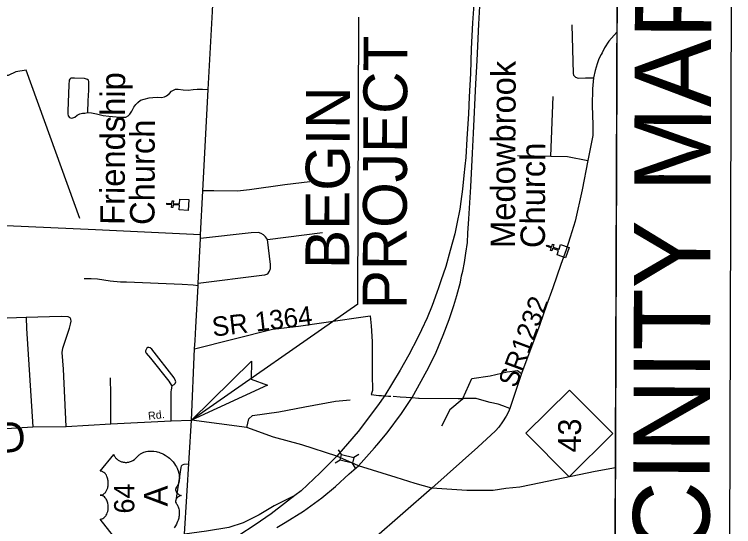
# Model space of a CAD drawing. Extents: x 2364794 to 2387902, y 795230 to 810426.
# Drawn here: x 2366377 to 2367318, y 801114 to 801786 of the extents above; entities that cross this region are included whole.
import ezdxf

# ---------------------------------------------------------------- set-up
doc = ezdxf.new("R2010")
doc.units = 0
for name, color, linetype in [('Default', 7, 'Continuous'), ('Old_Level_10', 7, 'Continuous'), ('Plot Label CELL', 7, 'Continuous'), ('Plot Shape CELL', 7, 'Continuous'), ('User Information Notes CELL', 7, 'Continuous')]:
    doc.layers.add(name, color=color, linetype=linetype)

msp = doc.modelspace()

# ---------------------------------------------------------------- linework, layer by layer
at = {"layer": 'Default'}
for p, q in [((2367310.68, 800398.89), (2367318.28, 802550.69)), ((2366826.27, 801406.05), (2366827.6, 801781.94)), ((2366826.27, 801406.05), (2366608.57, 801253.98)), ((2367046.3, 801236.64), (2367103.4, 801293.34)), ((2367103.4, 801293.34), (2367160.09, 801236.24)), ((2366843.94, 801287.32), (2366853.87, 801286.37)), ((2366897.38, 801283.49), (2366905.75, 801282.89)), ((2367103, 801179.55), (2367046.3, 801236.64)), ((2367160.09, 801236.24), (2367103, 801179.55)), ((2366489.2, 801187.02), (2366506.78, 801208.93)), ((2366506.78, 801208.93), (2366506.98, 801208.41)), ((2366506.98, 801208.41), (2366507.56, 801207.21)), ((2366538.58, 801207.19), (2366540.18, 801208.56)), ((2366540.18, 801208.56), (2366540.93, 801209.11)), ((2366540.93, 801209.11), (2366541.78, 801209.67)), ((2366541.78, 801209.67), (2366542.65, 801210.19)), ((2366542.65, 801210.19), (2366543.59, 801210.71)), ((2366543.59, 801210.71), (2366544.41, 801211.12)), ((2366544.41, 801211.12), (2366546.29, 801211.88)), ((2366546.29, 801211.88), (2366548.12, 801212.44)), ((2366548.12, 801212.44), (2366549.09, 801212.7)), ((2366549.09, 801212.7), (2366551.24, 801213.1)), ((2366551.24, 801213.1), (2366552.31, 801213.25)), ((2366552.31, 801213.25), (2366554.41, 801213.41)), ((2366554.41, 801213.41), (2366556.96, 801213.41)), ((2366556.96, 801213.41), (2366559.37, 801213.21)), ((2366559.37, 801213.21), (2366562.19, 801212.74)), ((2366562.19, 801212.74), (2366563.87, 801212.36)), ((2366563.87, 801212.36), (2366565.83, 801211.78)), ((2366565.83, 801211.78), (2366567.53, 801211.21)), ((2366567.53, 801211.21), (2366570.03, 801210.2)), ((2366570.03, 801210.2), (2366571.85, 801209.3)), ((2366571.85, 801209.3), (2366573.97, 801208.14)), ((2366573.97, 801208.14), (2366575.25, 801207.34)), ((2366804.94, 801208.71), (2366800.96, 801215.12)), ((2366827.47, 801209.04), (2366821.05, 801205.06)), ((2366507.56, 801207.21), (2366508.11, 801206.26)), ((2366508.11, 801206.26), (2366509.17, 801204.75)), ((2366509.17, 801204.75), (2366509.76, 801204.1)), ((2366509.76, 801204.1), (2366510.36, 801203.45)), ((2366510.36, 801203.45), (2366511.01, 801202.85)), ((2366511.01, 801202.85), (2366511.62, 801202.32)), ((2366511.62, 801202.32), (2366512.5, 801201.68)), ((2366512.5, 801201.68), (2366513.38, 801201.11)), ((2366513.38, 801201.11), (2366514.35, 801200.55)), ((2366514.35, 801200.55), (2366515.19, 801200.13)), ((2366515.19, 801200.13), (2366516.96, 801199.45)), ((2366516.96, 801199.45), (2366518.07, 801199.12)), ((2366518.07, 801199.12), (2366519.02, 801198.91)), ((2366519.02, 801198.91), (2366520.98, 801198.65)), ((2366520.98, 801198.65), (2366521.91, 801198.58)), ((2366522.84, 801198.58), (2366523.81, 801198.62)), ((2366523.81, 801198.62), (2366524.75, 801198.71)), ((2366524.75, 801198.71), (2366525.72, 801198.88)), ((2366525.72, 801198.88), (2366526.58, 801199.03)), ((2366526.58, 801199.03), (2366527.63, 801199.3)), ((2366527.63, 801199.3), (2366528.85, 801199.68)), ((2366528.85, 801199.68), (2366530.03, 801200.16)), ((2366530.03, 801200.16), (2366531.95, 801201.16)), ((2366531.95, 801201.16), (2366533.9, 801202.44)), ((2366533.9, 801202.44), (2366534.99, 801203.36)), ((2366534.99, 801203.36), (2366535.93, 801204.26)), ((2366535.93, 801204.26), (2366537.08, 801205.62)), ((2366537.08, 801205.62), (2366537.73, 801206.35)), ((2366537.73, 801206.35), (2366538.58, 801207.19)), ((2366575.25, 801207.34), (2366576.63, 801206.42)), ((2366576.63, 801206.42), (2366578.21, 801205.26)), ((2366578.21, 801205.26), (2366579.89, 801203.9)), ((2366579.89, 801203.9), (2366581.66, 801202.27)), ((2366581.66, 801202.27), (2366582.97, 801200.96)), ((2366582.97, 801200.96), (2366584.5, 801199.24)), ((2366584.5, 801199.24), (2366585.35, 801198.2)), ((2366803.21, 801201.36), (2366796.8, 801197.39)), ((2366521.91, 801198.58), (2366522.84, 801198.58)), ((2366585.35, 801198.2), (2366586.46, 801196.72)), ((2366586.46, 801196.72), (2366587.8, 801194.69)), ((2366587.8, 801194.69), (2366588.95, 801192.68)), ((2366588.95, 801192.68), (2366589.82, 801190.98)), ((2366589.82, 801190.98), (2366590.46, 801189.47)), ((2366590.46, 801189.47), (2366591.19, 801187.52)), ((2366823.26, 801191.14), (2366819.29, 801197.55)), ((2366489.86, 801186.99), (2366489.2, 801187.02)), ((2366490.62, 801186.89), (2366489.86, 801186.99)), ((2366491.5, 801186.67), (2366490.62, 801186.89)), ((2366492.33, 801186.32), (2366491.5, 801186.67)), ((2366493.12, 801185.94), (2366492.33, 801186.32)), ((2366493.89, 801185.4), (2366493.12, 801185.94)), ((2366494.94, 801184.49), (2366493.89, 801185.4)), ((2366495.82, 801183.53), (2366494.94, 801184.49)), ((2366496.46, 801182.72), (2366495.82, 801183.53)), ((2366497.15, 801181.62), (2366496.46, 801182.72)), ((2366497.86, 801180.25), (2366497.15, 801181.62)), ((2366498.31, 801179.2), (2366497.86, 801180.25)), ((2366591.19, 801187.52), (2366592.08, 801184.28)), ((2366592.08, 801184.28), (2366592.32, 801183.1)), ((2366592.32, 801183.1), (2366592.52, 801181.69)), ((2366592.52, 801181.69), (2366592.65, 801180.38)), ((2366592.65, 801180.38), (2366592.72, 801179.11)), ((2366498.73, 801178), (2366498.31, 801179.2)), ((2366499.08, 801176.68), (2366498.73, 801178)), ((2366499.29, 801175.68), (2366499.08, 801176.68)), ((2366499.5, 801174.43), (2366499.29, 801175.68)), ((2366499.62, 801173.3), (2366499.5, 801174.43)), ((2366499.68, 801172.2), (2366499.62, 801173.3)), ((2366499.66, 801170.03), (2366499.69, 801171)), ((2366499.69, 801171), (2366499.68, 801172.2)), ((2366591.46, 801170.67), (2366590.83, 801169.08)), ((2366591.98, 801172.42), (2366591.46, 801170.67)), ((2366592.34, 801174.09), (2366591.98, 801172.42)), ((2366592.58, 801175.7), (2366592.34, 801174.09)), ((2366592.71, 801177.4), (2366592.58, 801175.7)), ((2366592.72, 801179.11), (2366592.71, 801177.4)), ((2366497, 801160.78), (2366497.88, 801162.52)), ((2366497.88, 801162.52), (2366498.26, 801163.38)), ((2366498.26, 801163.38), (2366498.58, 801164.26)), ((2366498.58, 801164.26), (2366498.92, 801165.38)), ((2366498.92, 801165.38), (2366499.2, 801166.53)), ((2366499.2, 801166.53), (2366499.4, 801167.67)), ((2366499.4, 801167.67), (2366499.57, 801168.84)), ((2366499.57, 801168.84), (2366499.66, 801170.03)), ((2366587.77, 801163.54), (2366587.72, 801162.49)), ((2366587.72, 801162.49), (2366587.92, 801161.5)), ((2366587.89, 801163.98), (2366587.77, 801163.54)), ((2366588.31, 801164.76), (2366587.89, 801163.98)), ((2366587.92, 801161.5), (2366588.32, 801160.49)), ((2366590.03, 801167.47), (2366588.31, 801164.76)), ((2366590.83, 801169.08), (2366590.03, 801167.47)), ((2366489.11, 801155.58), (2366490.14, 801155.65)), ((2366490.33, 801155.48), (2366489.11, 801155.58)), ((2366490.14, 801155.65), (2366490.77, 801155.75)), ((2366490.91, 801155.35), (2366490.33, 801155.48)), ((2366490.77, 801155.75), (2366491.4, 801155.92)), ((2366492.24, 801154.88), (2366490.91, 801155.35)), ((2366491.4, 801155.92), (2366492.06, 801156.17)), ((2366492.06, 801156.17), (2366492.99, 801156.64)), ((2366492.86, 801154.54), (2366492.24, 801154.88)), ((2366493.51, 801154.15), (2366492.86, 801154.54)), ((2366492.99, 801156.64), (2366493.78, 801157.15)), ((2366494.66, 801153.22), (2366493.51, 801154.15)), ((2366493.78, 801157.15), (2366494.93, 801158.13)), ((2366495.77, 801152.05), (2366494.66, 801153.22)), ((2366494.93, 801158.13), (2366495.51, 801158.74)), ((2366495.51, 801158.74), (2366495.96, 801159.29)), ((2366496.36, 801151.22), (2366495.77, 801152.05)), ((2366495.96, 801159.29), (2366497, 801160.78)), ((2366588.32, 801160.49), (2366588.64, 801159.87)), ((2366588.64, 801159.87), (2366589.17, 801159.06)), ((2366589.73, 801152.04), (2366589.05, 801151.21)), ((2366589.17, 801159.06), (2366589.66, 801158.44)), ((2366589.66, 801158.44), (2366590.37, 801157.68)), ((2366590.39, 801152.72), (2366589.73, 801152.04)), ((2366590.37, 801157.68), (2366590.97, 801157.16)), ((2366591.28, 801153.49), (2366590.39, 801152.72)), ((2366590.97, 801157.16), (2366591.43, 801156.76)), ((2366591.97, 801153.97), (2366591.28, 801153.49)), ((2366591.43, 801156.76), (2366592.64, 801155.99)), ((2366592.75, 801154.44), (2366591.97, 801153.97)), ((2366592.64, 801155.99), (2366593.21, 801155.72)), ((2366593.66, 801154.83), (2366592.75, 801154.44)), ((2366593.21, 801155.72), (2366593.95, 801155.43)), ((2366595.04, 801155.18), (2366593.66, 801154.83)), ((2366593.95, 801155.43), (2366595.04, 801155.18)), ((2366497.04, 801150.17), (2366496.36, 801151.22)), ((2366497.73, 801148.85), (2366497.04, 801150.17)), ((2366498.22, 801147.66), (2366497.73, 801148.85)), ((2366498.66, 801146.37), (2366498.22, 801147.66)), ((2366498.95, 801145.22), (2366498.66, 801146.37)), ((2366499.42, 801142.72), (2366498.95, 801145.22)), ((2366499.59, 801140.46), (2366499.42, 801142.72)), ((2366587.7, 801148.19), (2366587.65, 801147.54)), ((2366587.65, 801147.54), (2366587.66, 801147.01)), ((2366587.66, 801147.01), (2366587.82, 801146.27)), ((2366587.9, 801148.98), (2366587.7, 801148.19)), ((2366587.82, 801146.27), (2366588.54, 801145.28)), ((2366588.15, 801149.62), (2366587.9, 801148.98)), ((2366588.52, 801150.33), (2366588.15, 801149.62)), ((2366589.05, 801151.21), (2366588.52, 801150.33)), ((2366588.54, 801145.28), (2366589.18, 801144.33)), ((2366589.18, 801144.33), (2366589.82, 801143.31)), ((2366589.82, 801143.31), (2366590.46, 801142.08)), ((2366498.35, 801132.44), (2366498.9, 801134.33)), ((2366498.9, 801134.33), (2366499.3, 801136.26)), ((2366499.3, 801136.26), (2366499.54, 801138.38)), ((2366499.54, 801138.38), (2366499.59, 801140.46)), ((2366590.46, 801142.08), (2366590.87, 801141.19)), ((2366590.87, 801141.19), (2366591.28, 801140.12)), ((2366591.28, 801140.12), (2366591.7, 801138.87)), ((2366591.7, 801138.87), (2366592.04, 801137.52)), ((2366592.04, 801137.52), (2366592.31, 801136.13)), ((2366592.31, 801136.13), (2366592.5, 801134.91)), ((2366592.5, 801134.91), (2366592.61, 801133.6)), ((2366592.61, 801133.6), (2366592.65, 801132.42)), ((2366489.05, 801124.13), (2366489.96, 801124.19)), ((2366506.47, 801102.1), (2366489.05, 801124.13)), ((2366489.96, 801124.19), (2366491.04, 801124.4)), ((2366491.04, 801124.4), (2366491.6, 801124.57)), ((2366491.6, 801124.57), (2366492.66, 801125.07)), ((2366492.66, 801125.07), (2366493.93, 801125.9)), ((2366493.93, 801125.9), (2366495.16, 801127.06)), ((2366495.16, 801127.06), (2366496.24, 801128.36)), ((2366496.24, 801128.36), (2366496.82, 801129.24)), ((2366496.82, 801129.24), (2366497.63, 801130.74)), ((2366497.63, 801130.74), (2366498.35, 801132.44)), ((2366591.45, 801124.21), (2366590.98, 801122.72)), ((2366591.84, 801125.66), (2366591.45, 801124.21)), ((2366592.16, 801127.04), (2366591.84, 801125.66)), ((2366592.41, 801128.7), (2366592.16, 801127.04)), ((2366592.53, 801130.03), (2366592.41, 801128.7)), ((2366592.63, 801131.19), (2366592.53, 801130.03)), ((2366592.65, 801132.42), (2366592.63, 801131.19)), ((2366587.5, 801115.56), (2366585.71, 801112.99)), ((2366588.76, 801117.75), (2366587.5, 801115.56)), ((2366589.48, 801119.13), (2366588.76, 801117.75)), ((2366590.36, 801121.13), (2366589.48, 801119.13)), ((2366590.98, 801122.72), (2366590.36, 801121.13))]:
    msp.add_line(p, q, dxfattribs=at)
for points in [[(2365221.07, 800406.27), (2365228.68, 802558.07), (2367168.28, 802551.22), (2367160.68, 800399.42)], [(2365221.07, 800406.27), (2365228.68, 802558.07), (2367168.28, 802551.22), (2367160.68, 800399.42)], [(2366592.52, 801529.31), (2366592.91, 801535.52), (2366584.6, 801536.06), (2366584.37, 801532.57), (2366582.63, 801532.69), (2366582.86, 801536.18), (2366576.3, 801536.61), (2366576.41, 801538.36), (2366582.98, 801537.93), (2366583.21, 801541.42), (2366584.95, 801541.3), (2366584.72, 801537.81), (2366593.03, 801537.27), (2366593.45, 801543.56), (2366605.07, 801542.79), (2366604.13, 801528.54)], [(2367087.16, 801470.35), (2367089.17, 801476.24), (2367081.3, 801478.95), (2367080.16, 801475.64), (2367078.51, 801476.21), (2367079.65, 801479.52), (2367073.43, 801481.66), (2367074, 801483.32), (2367080.22, 801481.17), (2367081.36, 801484.48), (2367083.01, 801483.91), (2367081.87, 801480.61), (2367089.74, 801477.9), (2367091.81, 801483.85), (2367102.82, 801480.06), (2367098.17, 801466.56)], [(2366819.29, 801197.55), (2366803.2, 801201.33), (2366804.97, 801208.84), (2366821.05, 801205.06)]]:
    msp.add_lwpolyline(points, close=True, dxfattribs=at)
for points in [[(2366853.87, 801286.37), (2366857.53, 801286.02), (2366862.3, 801285.75)], [(2366862.3, 801285.75), (2366866.69, 801285.49), (2366869.76, 801285.33)], [(2366605.33, 801196.12), (2366598.71, 801195.84), (2366596.27, 801195.03), (2366595.25, 801193.82), (2366594.63, 801191.79), (2366587.98, 801148.76)]]:
    msp.add_lwpolyline(points, dxfattribs=at)
at = {"layer": 'Old_Level_10'}
msp.add_line((2367160.68, 800399.42), (2367168.28, 802551.22), dxfattribs=at)
msp.add_lwpolyline([(2366708.16, 801299.72), (2366608.57, 801253.98), (2366687.27, 801331.23), (2366686.75, 801307.59)], close=True, dxfattribs=at)
at = {"layer": 'Plot Label CELL'}
for p, q in [((2367124.55, 801702.37), (2367134.81, 801702.62)), ((2367078.96, 801599.7), (2367082.19, 801678.01)), ((2367035.35, 801600.59), (2367078.96, 801599.7)), ((2366708.19, 801490.49), (2366779.91, 801499.63)), ((2366392.08, 801388.36), (2366349.47, 801386.86)), ((2366502.95, 801287.64), (2366502.71, 801309.18)), ((2366582.34, 801293.23), (2366583.3, 801299.15))]:
    msp.add_line(p, q, dxfattribs=at)
for points in [[(2367106.5, 801771.81), (2367108.36, 801708.21), (2367108.81, 801706.02), (2367109.87, 801704.74), (2367111.34, 801703.26), (2367114.85, 801702.14), (2367124.55, 801702.37)], [(2367165.49, 801762.42), (2367155.03, 801750.39), (2367149.05, 801741.82), (2367146.01, 801735.28), (2367144.71, 801733.07), (2367141.92, 801727.16), (2367140.34, 801723.59), (2367139.49, 801720.89), (2367137.06, 801712.03), (2367134.81, 801702.62), (2367133.56, 801688.22), (2367133.29, 801666.24), (2367134.18, 801640.87), (2367133.89, 801626.7)], [(2366472.83, 801656.82), (2366473.41, 801672.08), (2366474.33, 801686.1), (2366474.37, 801697.16), (2366473.85, 801699.26), (2366472.63, 801700.32), (2366468.6, 801701.56), (2366455.44, 801702.13), (2366450.7, 801701.97), (2366449.29, 801700.58), (2366448.41, 801699.18), (2366448.04, 801693.39), (2366446.68, 801658.84), (2366446.67, 801655.16), (2366447.01, 801652.52), (2366448.76, 801650.24), (2366451.04, 801649.53), (2366453.15, 801649.87), (2366455.96, 801650.91), (2366459.13, 801653.36), (2366462.47, 801655.1), (2366465.8, 801655.97), (2366468.96, 801656.31), (2366472.83, 801656.82)], [(2366472.83, 801656.82), (2366477.74, 801656.63), (2366484.4, 801655.37), (2366493.17, 801652.89), (2366500.54, 801652.16), (2366510.19, 801651.42), (2366518.26, 801650.87), (2366522.65, 801651.03), (2366525.64, 801652.42), (2366527.75, 801654.69), (2366530.4, 801658.72), (2366533.22, 801663.97), (2366535.52, 801667.65), (2366538.33, 801670.27), (2366541.85, 801673.06), (2366546.6, 801674.62), (2366553.1, 801676.18), (2366557.84, 801676.86), (2366563.98, 801677.19), (2366569.24, 801676.82), (2366573.28, 801677.34), (2366575.74, 801678.91), (2366579.62, 801681.87), (2366582.61, 801684.85), (2366584.9, 801686.24), (2366587.53, 801687.63), (2366591.22, 801687.62), (2366597.53, 801686.9), (2366604.2, 801686.35), (2366610.87, 801687.03), (2366616.14, 801687.36), (2366622.98, 801687.51), (2366630.55, 801687.32)], [(2367133.89, 801626.7), (2367127.63, 801594.08), (2367120.2, 801555.77), (2367111, 801514.61), (2367104.36, 801493.85), (2367098.94, 801476.88), (2367092.22, 801457.88), (2367081.58, 801427.34), (2367073.37, 801404.47), (2367064.78, 801379.37), (2367040.76, 801314.82), (2367025.38, 801269.01), (2367023.67, 801264.84), (2367020.67, 801259.33), (2367015.91, 801251.87), (2367010.72, 801244.84), (2367006.38, 801239.75), (2366983.63, 801218.36), (2366923.32, 801164.77)], [(2367078.96, 801599.7), (2367100.95, 801599.43), (2367127.63, 801594.08)], [(2366763.43, 801566.35), (2366730.65, 801562.07), (2366684.47, 801555.56), (2366668.75, 801553.78), (2366637.69, 801554.24), (2366623.48, 801554.46)], [(2366620.55, 801496.5), (2366482.99, 801503.36), (2366336.12, 801509.96), (2366282.43, 801513.49), (2366243.83, 801515.9), (2366150.3, 801521.11), (2366145.19, 801521.38), (2366044.51, 801526.78), (2365939.06, 801532.24), (2365896.96, 801538), (2365863.11, 801543.56), (2365836.88, 801547.42), (2365829.34, 801548.15), (2365823.73, 801548.7), (2365818.81, 801549.06), (2365807.58, 801548.93), (2365800.21, 801548.43)], [(2366617.52, 801433.53), (2366700.67, 801444.04), (2366704.52, 801444.38), (2366708.38, 801445.59), (2366710.68, 801449.27), (2366711.92, 801452.59), (2366711.94, 801458.03), (2366708.19, 801490.49)], [(2366708.19, 801490.49), (2366705.4, 801494.01), (2366702.95, 801496.65), (2366699.8, 801498.59), (2366696.29, 801499.66), (2366686.64, 801499.34), (2366620.36, 801492.12)], [(2366617.3, 801429.91), (2366610.64, 801430.85), (2366596.19, 801431.43), (2366523.73, 801434.67), (2366515.83, 801434.69), (2366502.06, 801435.88), (2366485.6, 801438.46), (2366477.07, 801439.26), (2366468.1, 801439.17)], [(2366444.48, 801245.73), (2366441.01, 801320.88), (2366439.1, 801342.52), (2366440.15, 801348.11), (2366449.06, 801374.27), (2366450.33, 801379.52), (2366450.94, 801383.46), (2366450.7, 801386.07), (2366449.57, 801388.05), (2366447.17, 801389.11), (2366437.77, 801389.66), (2366392.08, 801388.36)], [(2366392.08, 801388.36), (2366392.69, 801373.81), (2366400.79, 801245.11)], [(2366782.03, 801381.92), (2366842.43, 801390.78), (2366843.88, 801377.66), (2366844.94, 801357.09), (2366845.08, 801313.61), (2366845.48, 801292.84), (2366843.94, 801287.32)], [(2366612.63, 801347.25), (2366714.52, 801373.06), (2366748.8, 801377.05), (2366782.03, 801381.92)], [(2366583.3, 801299.15), (2366585.7, 801300.47), (2366587.22, 801301.78), (2366588.08, 801303.98), (2366587.86, 801305.51), (2366586.06, 801309.22), (2366556.66, 801347), (2366554.68, 801348.53), (2366552.94, 801348.95), (2366551.41, 801348.93), (2366550.32, 801348.26), (2366548.38, 801344.53), (2366548.17, 801343.21), (2366549.06, 801341.69), (2366554.81, 801335.19), (2366578.89, 801304.78), (2366582.43, 801299.35), (2366583.3, 801299.15)], [(2366963.59, 801282.09), (2366975.56, 801308.43), (2366999.47, 801312.14), (2367022, 801317.43), (2367035.37, 801318.84), (2367040.76, 801314.82)], [(2366582.15, 801253.06), (2366582.06, 801291.47), (2366582.34, 801293.23)], [(2366502.8, 801248.97), (2366502.8, 801254.52), (2366503.17, 801268.16), (2366502.95, 801287.64)], [(2366872.8, 801285.15), (2366881.93, 801284.59), (2366897.38, 801283.49)], [(2366681.23, 801244.45), (2366683.59, 801255.43), (2366688.26, 801260.06), (2366722.79, 801264.75), (2366757.13, 801271.54), (2366797.02, 801278.79), (2366816.39, 801280.74)], [(2366905.75, 801282.89), (2366906.7, 801282.83), (2366957.49, 801282.3), (2366963.59, 801282.09)], [(2366963.59, 801282.09), (2366962.76, 801281.01), (2366946.95, 801267.51), (2366935.82, 801245.83)], [(2367025.38, 801269.01), (2367015.96, 801272.86), (2367010.03, 801274.78), (2366999.52, 801276.86), (2366988.65, 801280.29), (2366981.11, 801282.11), (2366963.59, 801282.09)], [(2365883.31, 801194.17), (2365923.88, 801198.32), (2366005.19, 801208.19), (2366040.96, 801213.55), (2366060.86, 801216.45), (2366088.81, 801220.19), (2366143.18, 801226.76), (2366187.52, 801232.81), (2366212.86, 801234.35), (2366246.94, 801236.16), (2366291.51, 801239.37), (2366308.13, 801238.86), (2366358.84, 801242.59), (2366400.79, 801245.11), (2366444.48, 801245.73), (2366502.8, 801248.97), (2366582.15, 801253.06), (2366608.57, 801253.98)], [(2366681.23, 801244.45), (2366608.57, 801253.98)], [(2366798.8, 801206.63), (2366752.99, 801221.37), (2366715.84, 801231.64), (2366681.23, 801244.45)], [(2366827.07, 801194.06), (2366798.8, 801206.63)], [(2366923.32, 801164.77), (2366901.37, 801170.77), (2366876.46, 801178.88), (2366827.07, 801194.06)], [(2367163.47, 801191.25), (2367137.03, 801186.42), (2367053.29, 801169.17), (2367038.28, 801166.27), (2367020.1, 801164.22), (2367003.4, 801161.95), (2366968.95, 801161.65), (2366923.32, 801164.77)], [(2366923.32, 801164.77), (2366809.38, 801065.16), (2366769.88, 801030.29), (2366731.88, 800998.7), (2366709.97, 800981.02), (2366639.98, 800922.63), (2366602.18, 800891.19), (2366598.11, 800888.97), (2366593.63, 800886.75), (2366588.34, 800884.74)]]:
    msp.add_lwpolyline(points, dxfattribs=at)
at = {"layer": 'Plot Shape CELL'}
for points in [[(2366620.55, 801496.5), (2366623.48, 801554.46), (2366630.55, 801687.32), (2366635.98, 801789.2), (2366637.22, 801817.52), (2366639.18, 801851.8), (2366640.69, 801880.74), (2366645.59, 801975.26)], [(2366980.2, 801829.83), (2366976.55, 801774.3), (2366974.89, 801740.41), (2366973.64, 801708.18), (2366971.92, 801677.49), (2366971.25, 801655.13), (2366969.15, 801622.66), (2366967.57, 801597.87), (2366966.62, 801586.53), (2366964.99, 801574.5), (2366963.33, 801556.35), (2366961.01, 801540.46), (2366959.84, 801530.48), (2366955.91, 801510.97), (2366953.13, 801498.04), (2366947.38, 801476.27), (2366941.63, 801455.18), (2366935.2, 801436.36), (2366931.76, 801427.29), (2366929.69, 801421.17), (2366923.5, 801403.94), (2366917.31, 801388.07), (2366909.76, 801372.2), (2366904.73, 801362.23), (2366893.29, 801339.57), (2366881.64, 801319.41), (2366861.67, 801286.25), (2366861.53, 801286.11), (2366851.94, 801272.52), (2366826.93, 801238.82), (2366798.8, 801206.63)], [(2366827.07, 801194.06), (2366848.21, 801217.48), (2366851.29, 801220.94), (2366864.66, 801237.37), (2366883.6, 801262.47), (2366897.39, 801283.51), (2366904.49, 801296.17), (2366919.13, 801323.36), (2366928.74, 801343.08), (2366937.9, 801365.29), (2366945.7, 801385.92), (2366951.89, 801404.29), (2366955.8, 801417.21), (2366960.63, 801434.68), (2366962.25, 801443.07), (2366963.64, 801448.97), (2366965.95, 801460.31), (2366967.81, 801472.79), (2366969.9, 801486.86), (2366970.4, 801498.89), (2366971.6, 801517.72), (2366974.17, 801559.71), (2366976.3, 801603.59), (2366977.72, 801629.94), (2366980.97, 801694.37), (2366982.53, 801724.94), (2366984.81, 801772.63), (2366986.37, 801804.25)], [(2366608.57, 801253.98), (2366612.63, 801347.25), (2366613.21, 801358.26), (2366614.12, 801375.64), (2366617.3, 801429.91), (2366617.52, 801433.53), (2366620.36, 801492.12), (2366620.55, 801496.5)], [(2366599.61, 801104.46), (2366608.57, 801253.98)], [(2366798.8, 801206.63), (2366790.93, 801198.75), (2366776.9, 801184.84), (2366752.04, 801161.47), (2366744.07, 801155.26)], [(2366720.42, 801113.24), (2366731.22, 801119.63), (2366755.27, 801134.44), (2366779.33, 801152.01), (2366797.05, 801166.97), (2366814.9, 801183.52), (2366827.07, 801194.06)], [(2366744.07, 801155.26), (2366730.49, 801144.67), (2366712.91, 801131.16), (2366691.76, 801116.87), (2366670.35, 801102.85), (2366655.42, 801093.55), (2366622.53, 801075.74), (2366597.79, 801062.52)], [(2366744.07, 801155.26), (2366716.86, 801141.43), (2366697.24, 801129.77), (2366676.25, 801119.56), (2366657.44, 801113.08), (2366628.37, 801108.52), (2366599.61, 801104.46)]]:
    msp.add_lwpolyline(points, dxfattribs=at)
at = {"layer": 'User Information Notes CELL'}
msp.add_lwpolyline([(2366462.41, 801518), (2366392, 801712.25), (2366378.43, 801710.32), (2366368.56, 801705.65), (2366333.77, 801705.35), (2366290.1, 801721.35), (2366253.45, 801741.93), (2366234.01, 801762.67), (2366219.12, 801796.18), (2366210.57, 801823.43), (2366195.87, 801842.41), (2366156.6, 801865.73), (2366121.86, 801873.61), (2366084.25, 801871.46), (2366068.93, 801868.55), (2366036.28, 801868.24), (2366022.41, 801874.52), (2366016.73, 801882.62), (2366015.99, 801892.69)], dxfattribs=at)

# ---------------------------------------------------------------- texts
at = {"layer": 'Default'}
for s, height, rotation, p in [('VICINITY MAP', 100, 89.79762, (2367286.06, 800950.79)), ('PROJECT', 57.409, 89.79762, (2366890.04, 801399.17)), ('Medowbrook', 32.036, 89.79762, (2367032.2, 801479.44)), ('Friendship', 32.036, 89.79762, (2366521.09, 801509.72)), ('BEGIN ', 57.409, 89.79762, (2366815.09, 801451.9)), ('Church', 32.036, 89.79762, (2366560.14, 801509.58)), ('Church', 32.036, 89.79762, (2367071.25, 801479.31)), ('Rd.', 10.388, 6.90793, (2366552.41, 801254.17)), ('SPRINGFIELD RD', 39.628, 6.73691, (2365952.18, 801162.08)), ('43', 29.9, 89.79762, (2367118.44, 801211.47)), ('64', 26.483, 89.79762, (2366533.72, 801131.46)), ('A', 30.75, 89.79762, (2366577.3, 801140.83))]:
    msp.add_text(s, height=height, rotation=rotation, dxfattribs=at).set_placement(p)
at = {"layer": 'Plot Label CELL'}
for s, rotation, p in [('SR1232', 69.58753, (2367033.4, 801295.06)), ('SR 1364', 6.63921, (2366636.92, 801363.32))]:
    msp.add_text(s, height=25.362, rotation=rotation, dxfattribs=at).set_placement(p)

doc.saveas('drawing.dxf')
